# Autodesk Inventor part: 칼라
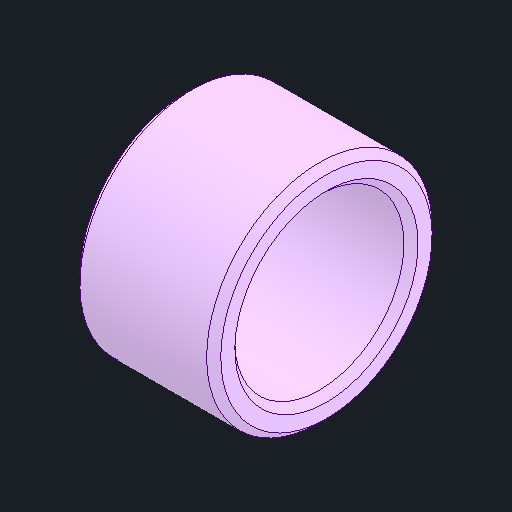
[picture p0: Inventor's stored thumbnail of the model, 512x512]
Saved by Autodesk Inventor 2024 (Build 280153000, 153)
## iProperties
Created: 2024-05
Part Number: 칼라
Material: 강철, 합금
Document SubType Name: Modeling
Designer: kh_501
Density: 7.73 g/cm^3
Appearance: 기본값
Sending System: Autodesk Inventor 2025
Preprocessor: ST-DEVELOPER v20
Author: jhkim
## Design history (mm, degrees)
feature "솔리드1"
node "솔리드2"
